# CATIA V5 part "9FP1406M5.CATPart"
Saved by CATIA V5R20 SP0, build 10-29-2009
Part number: 9FP1406M5
Revision: ANY
Definition: UNKNOWN
Nomenclature: 9FP1406M5
Source: Unknown
Bounding box of the stored display mesh (mm): x -6.727 to 6.727, y 0 to 6, z -6.9 to 6.9
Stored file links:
  C:\Users\Utente\Desktop\IO LAVORO\3D X SITO CF\CUMSA\3D files PW\pw081030\pw081030_ejection\9FP1406M5.CATPart
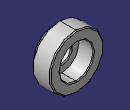
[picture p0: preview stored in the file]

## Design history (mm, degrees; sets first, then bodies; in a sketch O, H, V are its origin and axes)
Body1 "Chaflán1" (main body)
  Solid1: solid without history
